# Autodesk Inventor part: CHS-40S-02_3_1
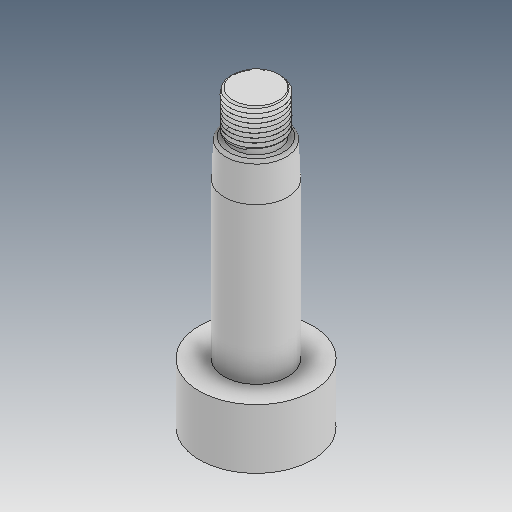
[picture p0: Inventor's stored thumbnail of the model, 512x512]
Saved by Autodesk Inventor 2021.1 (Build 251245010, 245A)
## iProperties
Created: 2019-05
Part Number: CHS-40S-02_3_1
Material: Ogólny
Document SubType Name: Modeling
Designer: user
Density: 1 g/cm^3
Appearance: Domyślna
Author: user
Revision Number: ÈÎºÎ
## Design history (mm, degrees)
feature "ÊäÈë1"
feature "ÊäÈë2"
node "Bryła1"
node "Bryła2"
